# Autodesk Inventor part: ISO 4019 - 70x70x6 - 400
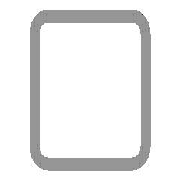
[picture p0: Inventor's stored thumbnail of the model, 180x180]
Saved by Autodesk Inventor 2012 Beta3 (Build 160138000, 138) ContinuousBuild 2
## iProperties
IsCustomPart: 1
Created: 2010-11
Part Number: ISO 4019 - 70x70x6 - 400
Material: Steel, Mild
Description: Structural steels - Cold-formed, welded, structural hollow sections
Document SubType Name: Modeling
Standard: ISO
Designer: Beta-8540w
Standard Revision: Second edition 2001-09-01
Standards Organization: ISO
Language: en-US
Size Designation: 70x70x6
Categories: <MemberInstance><Categories><Category DisplayName="Structural Shapes" InternalName="089c4875-fa83-4c05-b084-43b9cc11f5ed" Mnemonic="GRDR"><CategoryParameter Dis
Stock Number: 70x70x6
Density: 7.86 g/cm^3
_CCFamilyMember: 28
_CCFamilyDisplayName: ISO 4019 (Square) - Structural steels - Cold-formed, welded, structural hollow sections
_FrameMemberDoc: Frame Member File
_Version: 15.0.0
_GetPNFromCC: 1
G_L: 400.000 mm
G_W: 70.000 mm
G_H: 70.000 mm
Author: Beta-8540w
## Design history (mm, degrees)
node "Start plane"
node "End plane"
sketch "Sketch"
  geometry: L1 (-35, -23)-(-35, 23); L2 (-23, 35)-(23, 35); L3 (35, 23)-(35, -23); L4 (23, -35)-(-23, -35); L5 (-23, 29)-(23, 29); L6 (29, 23)-(29, -23); L7 (23, -29)-(-23, -29); L8 (-29, -23)-(-29, 23); L9 (0, 52.479)-(0, -52.479) reference; L10 (-52.479, 0)-(52.479, 0) reference; A1 r 12 centre (-23, -23) between (-35, -23) and (-23, -35); A2 r 12 centre (23, 23) between (35, 23) and (23, 35); A3 r 12 centre (-23, 23) between (-23, 35) and (-35, 23); A4 r 12 centre (23, -23) between (23, -35) and (35, -23); A5 r 6 centre (-23, 23) between (-23, 29) and (-29, 23); A6 r 6 centre (23, 23) between (29, 23) and (23, 29); A7 r 6 centre (23, -23) between (23, -29) and (29, -23); A8 r 6 centre (-23, -23) between (-29, -23) and (-23, -29)
  constraints: 16 end point, 16 point on circle, 8 centre point, 8 tangent, 4 parallel, 3 equal radius, 2 perpendicular, 7 other
  dimensions: "d7" = 12 radius of A1 (= G_IR); "d9" = 70 distance between parallel lines of L1 L3 (= G_W); "d11" = 70 distance between parallel lines of L2 L4 (= G_H); "d12" = 6 distance between parallel lines of L3 L6 (= G_T); "d15" = 35 distance between parallel lines of L9 L3 (= 0.5 x d9); "d16" = 35 distance between parallel lines of L2 L10 (= 0.5 x d11)
extrude "Body" new body sketch "Sketch" stored distance "d3" = 400 (= G_L); taper "d4" = 0 deg
node "Driven Length"
  sketch "Sketch3"
    geometry: L1 (0, 0)-(10, 0) reference
    constraints: 2 end point, 1 horizontal
  workplane "Work Plane3"
  sketch "Sketch4"
    geometry: L1 (-2, 0)-(12, 0) reference; L2 (-2, 400)-(12, 400) reference
    dimensions: "d18" = 400 distance between parallel lines of L1 L2 (derived)
sketch "Sketch5"
  geometry: L1 (0, -46)-(0, 0) reference; C1 r 20 at (35, -23); 2 further points
  constraints: 1 centre point, 1 horizontal alignment, 1 midpoint
  dimensions: "d19" = 40 diameter of C1; "d20" = 35 distance of point (0, -23) C1.centre
extrude "Extrusion2" cut sketch "Sketch5" stored distance "d21" = 10; taper "d22" = 0 deg
sketch "Sketch6"
  geometry: L1 (400, 46)-(400, 0) reference; C1 r 17 at (365, 23); 2 further points
  constraints: 1 centre point, 1 horizontal alignment, 1 midpoint
  dimensions: "d23" = 34 diameter of C1; "d24" = 35 distance of point (400, 23) C1.centre
extrude "Extrusion3" cut sketch "Sketch6" stored distance "d25" = 10; taper "d26" = 0 deg
body "Solid1"
other parameters: "G_W" = 70 [user parameter; used in 1 equation term], "G_H" = 70 [user parameter; used in 1 equation term], "G_T" = 6 [user parameter; used in 1 equation term], "G_IR" = 12 [user parameter; used in 1 equation term], "G_L" = 400 (= d18) [user parameter; used in 1 equation term], "G_OFFSET_START" = 0 [user parameter; used in 1 equation term], "G_OFFSET_END" = 0 [user parameter; used in 1 equation term], "d13" = 0 (computed from G_OFFSET_START), "d17" = 90 deg, "MAS" = 1.13 [user parameter]
